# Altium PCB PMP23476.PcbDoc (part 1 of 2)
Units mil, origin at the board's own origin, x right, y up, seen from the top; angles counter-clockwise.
Board outline 965 x 1259.84 mil, 4 copper layers (Top Layer, Signal Layer 1, Signal Layer 2, Bottom Layer), stack 62 mil thick; 45 components, 25 nets, 111 pads, 20 vias.
Unrouted connection lines stored in the file: 2.
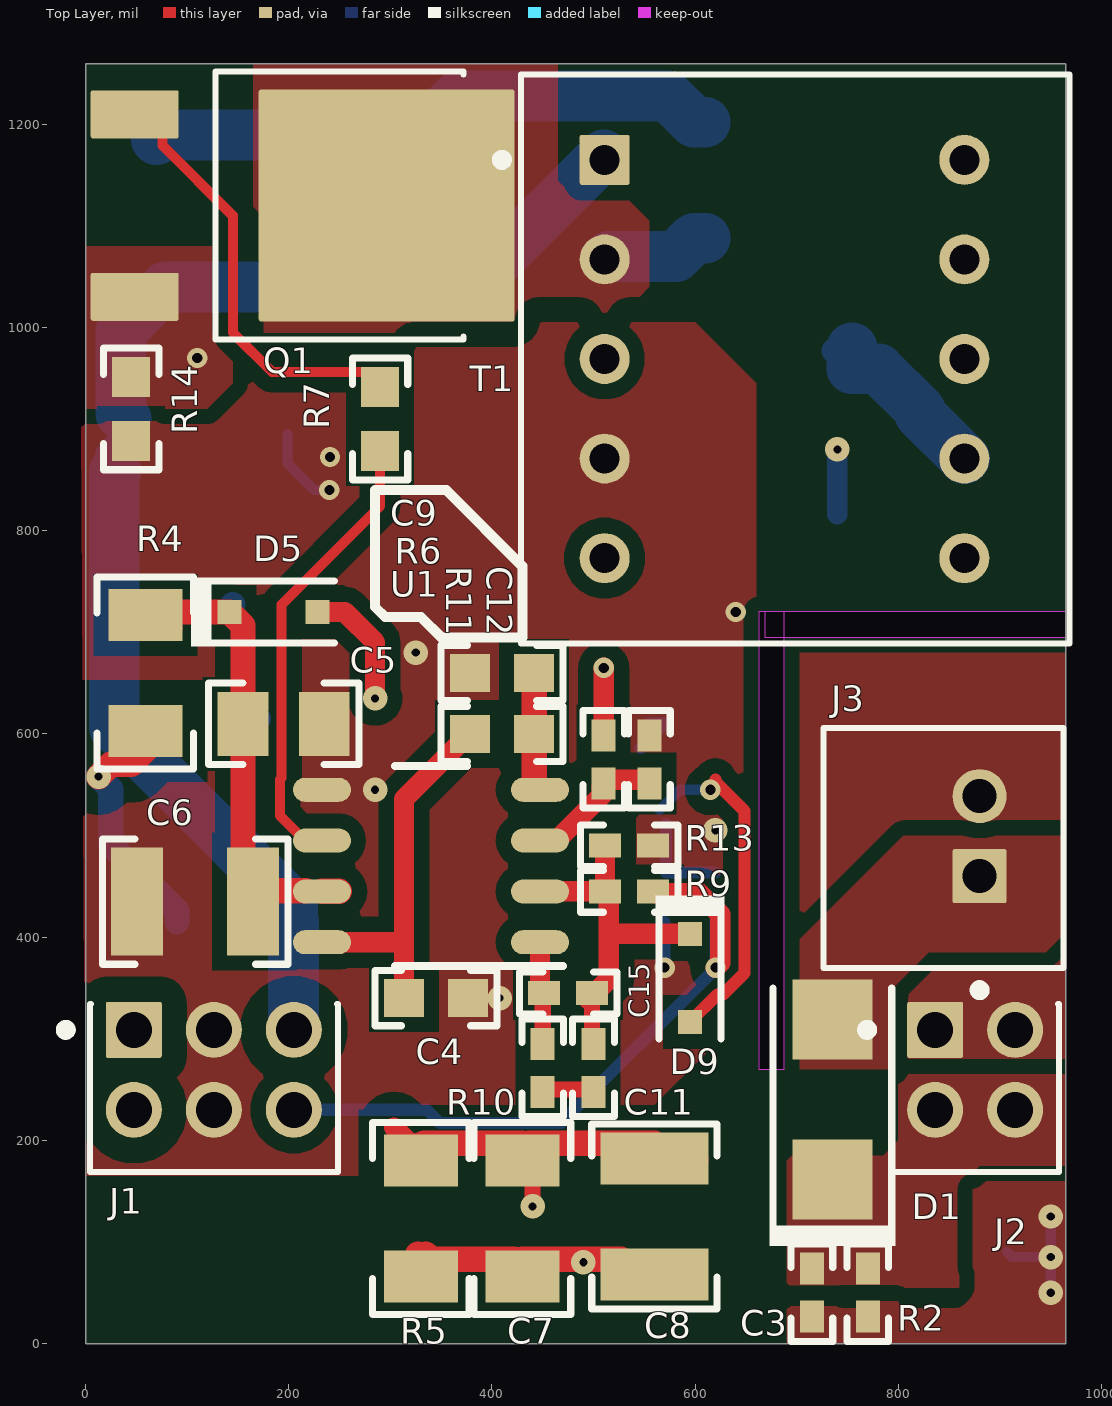
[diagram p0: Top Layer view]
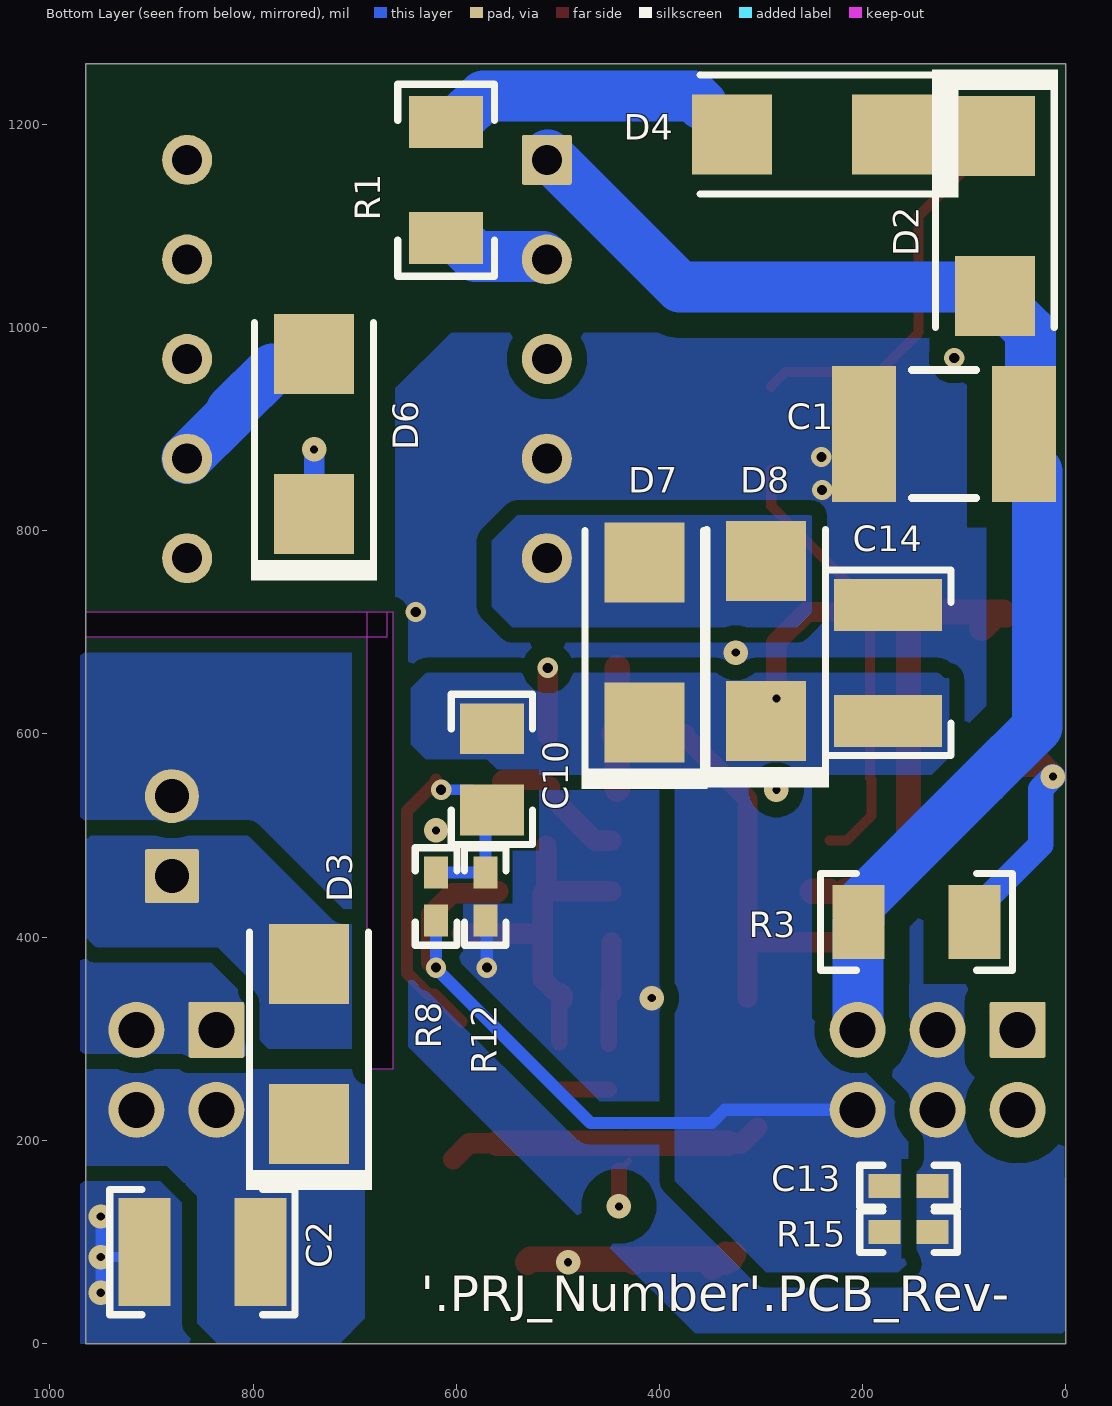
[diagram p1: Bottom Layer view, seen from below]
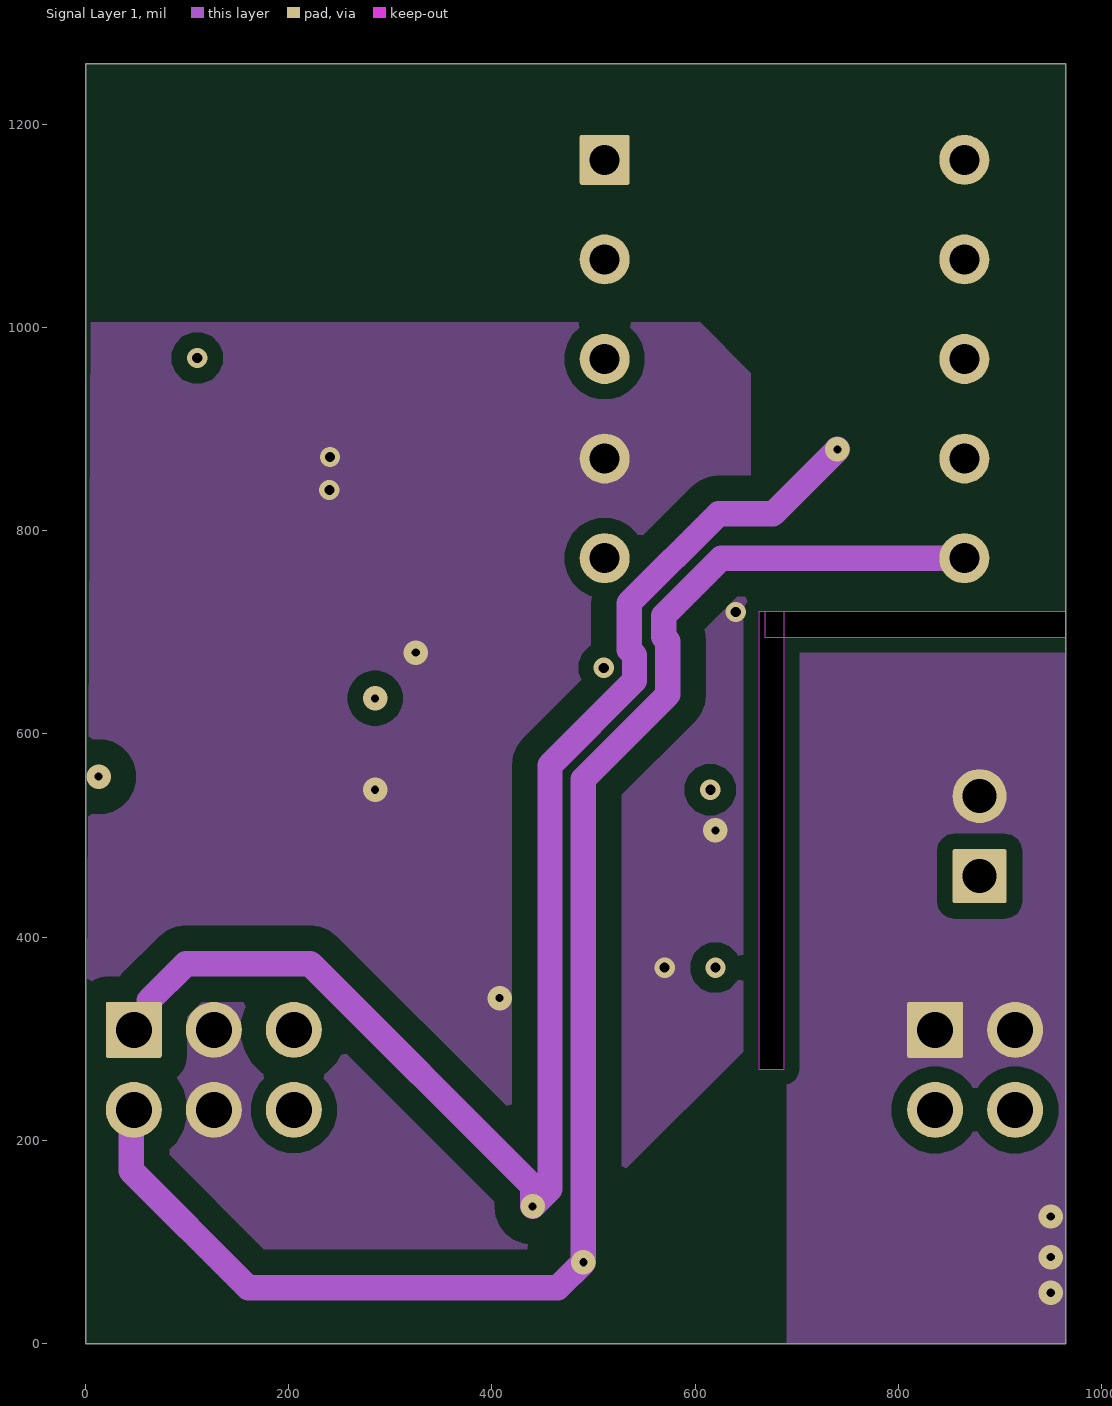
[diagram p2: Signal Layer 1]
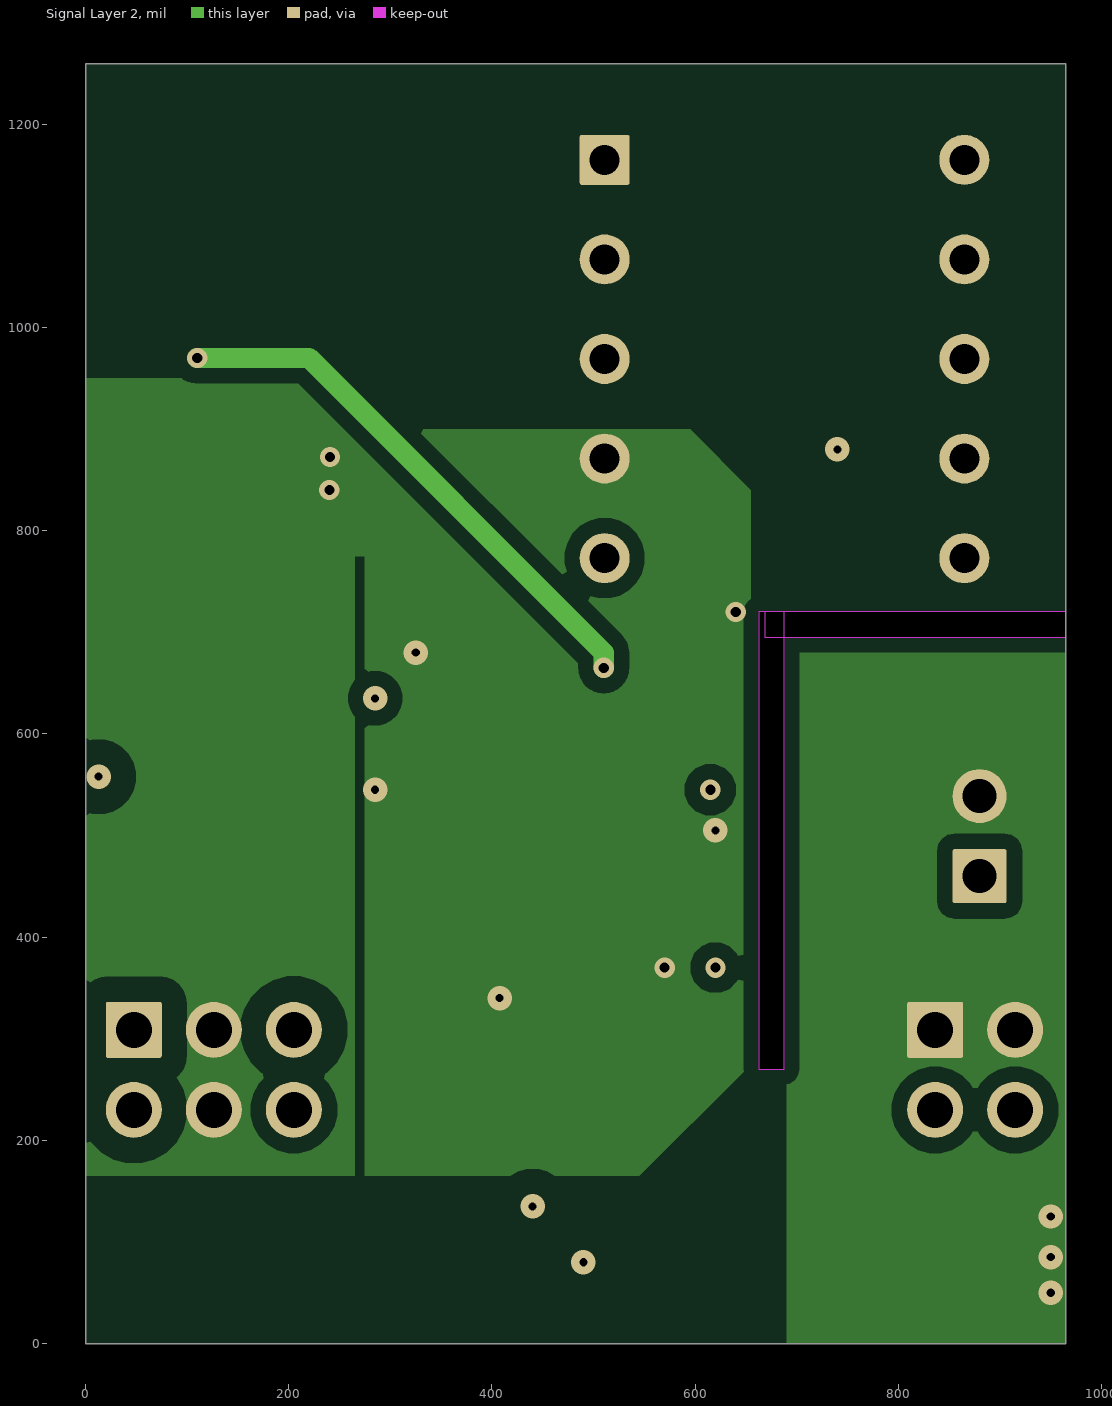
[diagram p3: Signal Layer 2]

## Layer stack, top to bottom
Top Solder: solder mask 0.4, Solder Resist, Dk 3.5
Top Layer: signal copper 1.4
Dielectric 1: prepreg 8, Dk 4.2
Dielectric1: prepreg 8, Dk 4.2
Signal Layer 1: signal copper 1.4
Dielectric 3: core 24.4, FR-4, Dk 4.2
Signal Layer 2: signal copper 1.4
Dielectric 2: prepreg 8, Dk 4.2
Dielectric 4: prepreg 8, Dk 4.2
Bottom Layer: signal copper 1.4
Bottom Solder: solder mask 0.4, Solder Resist, Dk 3.5

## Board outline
0,0 965,0 964.57,1259.84 0,1259.84
cut-out: 662.5,270 687.5,270 687.5,720 662.5,720
cut-out: 965,695 965,720 668.75,720 668.75,695

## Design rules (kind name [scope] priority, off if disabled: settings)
AcuteAngle [All] p1: minimum=4.50000000000000E+0001 checktracksonly=FALSE
AssemblyTestPointUsage [All] p1: valid=2
Clearance Clearance_1 [InNetClass('HV') vs InNet('GND_PRI')] p1: gap=25 ignorepadtopadclearanceinfootprint=TRUE except(0: Arc-Hole Track-Hole SMDPad-Hole THPad-Hole Via-Hole Fill-Hole Poly-Hole Region-Hole Text-Hole)
Clearance Clearance_Keepouts [((IsTrack Or IsArc) And Not InPoly) And IsFree and IsKeepOut vs ((IsTrack Or IsArc) And Not InPoly) And IsFree and IsKeepOut] p2: gap=0 ignorepadtopadclearanceinfootprint=FALSE
Clearance Clearance_BoardEdge_MountingHoles [OnCopper and InComponentClass('Mounting Holes') vs IsKeepOut] p3: gap=40 ignorepadtopadclearanceinfootprint=FALSE except(0: Arc-Hole Track-Hole SMDPad-Hole THPad-Hole Via-Hole Fill-Hole Poly-Hole Region-Hole Text-Hole)
Clearance Clearance_BoardEdge_Poly [OnCopper and InPoly vs IsKeepOut] p4: gap=25 ignorepadtopadclearanceinfootprint=FALSE except(0: Arc-Hole Track-Hole SMDPad-Hole THPad-Hole Via-Hole Fill-Hole Poly-Hole Region-Hole Text-Hole)
Clearance Clearance_BoardEdge [OnCopper and Not InComponentClass('Logo') and not InComponentClass('FiducialMark') and not InRegion(1000,500,4000,800) and Not IsKeepout vs IsKeepOut] p5: gap=75 ignorepadtopadclearanceinfootprint=FALSE except(0: Arc-Hole Track-Hole SMDPad-Hole THPad-Hole Via-Hole Fill-Hole Poly-Hole Region-Hole Text-Hole)
Clearance Clearance_Poly [InPolygon] p6: gap=15 ignorepadtopadclearanceinfootprint=FALSE except(0: Arc-Hole Track-Hole SMDPad-Hole THPad-Hole Via-Hole Fill-Hole Poly-Hole Region-Hole Text-Hole)
Clearance [All] p7: gap=7.87 ignorepadtopadclearanceinfootprint=FALSE except(0: Arc-Hole Track-Hole SMDPad-Hole THPad-Hole Via-Hole Fill-Hole Poly-Hole Region-Hole Text-Hole)
ComponentClearance ComponentClearance_MountingHoles_FiducialMarks [InComponentClass('Mounting Holes') vs InComponentClass('FiducialMark')] p1: gap=20 collisioncheckmode=3 verticalgap=10 showdistances=FALSE
ComponentClearance ComponentClearance_Shunt [InComponentClass('Header') vs InComponentClass('Shunt')] p2: gap=0 collisioncheckmode=3 verticalgap=0 showdistances=FALSE
ComponentClearance ComponentClearance_Logo [InComponentClass('Logo')] p3: gap=5 collisioncheckmode=3 verticalgap=10 showdistances=FALSE
ComponentClearance ComponentClearance_ScrewToNut [(HasFootprint('NY PMS 440 0025 PH')) vs (HasFootprint('Keystone_1902C'))] p4: gap=20 collisioncheckmode=3 verticalgap=100000 showdistances=FALSE
ComponentClearance ComponentClearance_MountingHoles [InComponentClass('Mounting Holes')] p5: gap=20 collisioncheckmode=3 verticalgap=10 showdistances=FALSE
ComponentClearance ComponentClearance_SmallPassives [HasFootprint('0201*') or HasFootprint('0402*') or HasFootprint('0508') or HasFootprint('0603*') or HasFootprint('0612') or HasFootprint('0805*') or HasFootprint('0815*') or HasFootprint('0830*') or HasFootprint('1206*') or HasFootprint('1210*') or HasFootprint('1808*') or HasFootprint('1812*') or HasFootprint('1825*') or HasFootprint('2010*') or HasFootprint('2220*') or HasFootprint('2225*') or HasFootprint('2512*') or HasFootprint('2728*') or HasFootprint('3518*') vs HasFootprint('0201*') or HasFootprint('0402*') or HasFootprint('0508') or HasFootprint('0603*') or HasFootprint('0612') or HasFootprint('0805*') or HasFootprint('0815*') or HasFootprint('0830*') or HasFootprint('1206*') or HasFootprint('1210*') or HasFootprint('1808*') or HasFootprint('1812*') or HasFootprint('1825*') or HasFootprint('2010*') or HasFootprint('2220*') or HasFootprint('2225*') or HasFootprint('2512*') or HasFootprint('2728*') or HasFootprint('3518*')] p6: gap=20 collisioncheckmode=3 verticalgap=20 showdistances=FALSE
ComponentClearance ComponentClearance_THtoSMT [IsThruComponent vs IsSMTComponent] p7: gap=10 collisioncheckmode=3 verticalgap=10 showdistances=FALSE
ComponentClearance ComponentClearance_THtoTH [IsThruComponent vs IsThruComponent] p8: gap=10 collisioncheckmode=3 verticalgap=10 showdistances=FALSE
ComponentClearance [All] p9: gap=10 collisioncheckmode=3 verticalgap=10 showdistances=FALSE
DiffPairsRouting [All] p1: maxlimit=100 minlimit=10 mostfreqgap=10 toplayer_minwidth=15 toplayer_maxwidth=15 toplayer_prefwidth=15 midlayer1_minwidth=15 midlayer1_maxwidth=15 midlayer1_prefwidth=15 midlayer2_minwidth=15 midlayer2_maxwidth=15 midlayer2_prefwidth=15 bottomlayer_minwidth=15 bottomlayer_maxwidth=15 bottomlayer_prefwidth=15 maxuncoupledlength=1000
FabricationTestPointUsage TestPointUsage [All] p1: valid=2 allowmultiple=FALSE
FabricationTestpoint Testpoint [All] p1: side=3 testpointundercomponent=TRUE minsize=40 maxsize=100 preferedsize=60 minholesize=0 maxholesize=40 preferedholesize=32 testpointgrid=1 allowsidetop=TRUE allowsidebottom=TRUE usegrid=TRUE gridtolerance=0.01
FanoutControl Fanout_LCC [IsLCC] p1: bgadir=Out bgaviamode=Centered fanoutstyle=Auto fanoutdirection=Alternating viagrid=1 // Fanout_LCC (Default Rule)
FanoutControl Fanout_BGA [IsBGA] p2: bgadir=Out bgaviamode=Centered fanoutstyle=Auto fanoutdirection=Alternating viagrid=1 // Fanout_BGA (Default Rule)
FanoutControl Fanout_Default [All] p4: bgadir=Out bgaviamode=Centered fanoutstyle=Auto fanoutdirection=Alternating viagrid=1 // Fanout_Default (Default Rule)
FanoutControl Fanout_Small [(CompPinCount < 5)] p5: bgadir=Out bgaviamode=Centered fanoutstyle=Auto fanoutdirection=OutThenIn viagrid=1 // Fanout_Small (Default Rule)
Height [All] p1: minheight=0 maxheight=3000 prefheight=500
HoleSize [All] p1: absolutevalues=TRUE maxlimit=251 minlimit=7 maxpercent=80.000 minpercent=20.000
MinimumAnnularRing MinimumAnnularRing_ThermalPadVias [IsVia and InAnyComponent] p1: minimumring=5.91
MinimumAnnularRing [All] p2: minimumring=4.9
MinimumSolderMaskSliver MinimumSolderMaskSliver_Logo [InComponentClass('Logo') vs InComponentClass('Logo')] p1: minsoldermaskwidth=0.7
MinimumSolderMaskSliver [All] p2: minsoldermaskwidth=2
PlaneConnect [All] p1: planeconnectstyle=Direct reliefexpansion=10 reliefentries=4 reliefconductorwidth=10 reliefairgap=10
PolygonConnect PolygonConnect_13 [All vs IsNamedPolygon('Q900_4') Or  IsNamedPolygon('Q900_4') Or  IsNamedPolygon('5V') Or  IsNamedPolygon('L900_1') Or  IsNamedPolygon('D900_2') Or  IsNamedPolygon('D902_2') Or  IsNamedPolygon('GND_PRI') Or  IsNamedPolygon('SGND') Or  IsNamedPolygon('HSS') Or  IsNamedPolygon('HSS') Or  IsNamedPolygon('C901_2') Or  IsNamedPolygon('12VPL') Or  IsNamedPolygon('C901_2') Or  IsNamedPolygon('D901_1') Or  IsNamedPolygon('D902_2') Or  IsNamedPolygon('B+') Or  IsNamedPolygon('Q900_3')] p1: connectstyle=Direct reliefconductorwidth=10 reliefentries=4 polygonreliefangle="90 Angle" airgapwidth=10
PolygonConnect PolygonConnect_12 [All vs IsNamedPolygon('C901_2') Or  IsNamedPolygon('C901_2') Or  IsNamedPolygon('GND_PRI') Or  IsNamedPolygon('5V') Or  IsNamedPolygon('B+') Or  IsNamedPolygon('D900_2') Or  IsNamedPolygon('12VPL') Or  IsNamedPolygon('D902_2') Or  IsNamedPolygon('Q900_3') Or  IsNamedPolygon('Q900_4') Or  IsNamedPolygon('D901_1') Or  IsNamedPolygon('SGND') Or  IsNamedPolygon('D902_2') Or  IsNamedPolygon('L900_1') Or  IsNamedPolygon('Q900_4')] p2: connectstyle=Direct reliefconductorwidth=10 reliefentries=4 polygonreliefangle="90 Angle" airgapwidth=10
PolygonConnect PolygonConnect_11 [All vs IsNamedPolygon('B+') Or  IsNamedPolygon('Q900_3') Or  IsNamedPolygon('12VPL') Or  IsNamedPolygon('D902_2') Or  IsNamedPolygon('D901_1') Or  IsNamedPolygon('5V') Or  IsNamedPolygon('D902_2') Or  IsNamedPolygon('Q900_4') Or  IsNamedPolygon('L900_1') Or  IsNamedPolygon('C901_2') Or  IsNamedPolygon('C901_2') Or  IsNamedPolygon('D900_2') Or  IsNamedPolygon('SGND') Or  IsNamedPolygon('Q900_4')] p3: connectstyle=Direct reliefconductorwidth=10 reliefentries=4 polygonreliefangle="90 Angle" airgapwidth=10
PolygonConnect PolygonConnect_10 [All vs IsNamedPolygon('Q900_4') Or  IsNamedPolygon('D902_2') Or  IsNamedPolygon('B+') Or  IsNamedPolygon('D901_1') Or  IsNamedPolygon('D902_2') Or  IsNamedPolygon('Q900_3')] p4: connectstyle=Direct reliefconductorwidth=10 reliefentries=4 polygonreliefangle="90 Angle" airgapwidth=10
PolygonConnect PolygonConnect_9 [All vs IsNamedPolygon('C11_1') Or  IsNamedPolygon('Vin') Or  IsNamedPolygon('Vin') Or  IsNamedPolygon('5V') Or  IsNamedPolygon('D6_2') Or  IsNamedPolygon('Q3_3') Or  IsNamedPolygon('GND2') Or  IsNamedPolygon('GND2') Or  IsNamedPolygon('GND') Or  IsNamedPolygon('Q3_4') Or  IsNamedPolygon('12V5') Or  IsNamedPolygon('GND') Or  IsNamedPolygon('12V5') Or  IsNamedPolygon('D3_1')] p5: connectstyle=Direct reliefconductorwidth=10 reliefentries=4 polygonreliefangle="90 Angle" airgapwidth=10
PolygonConnect PolygonConnect_8 [All vs IsNamedPolygon('C11_1') Or  IsNamedPolygon('Vin') Or  IsNamedPolygon('12V5') Or  IsNamedPolygon('Q3_3') Or  IsNamedPolygon('GND2') Or  IsNamedPolygon('GND2') Or  IsNamedPolygon('5V') Or  IsNamedPolygon('Q3_4') Or  IsNamedPolygon('12V5')] p6: connectstyle=Direct reliefconductorwidth=10 reliefentries=4 polygonreliefangle="90 Angle" airgapwidth=10
PolygonConnect PolygonConnect_7 [All vs IsNamedPolygon('GND2') Or  IsNamedPolygon('GND2') Or  IsNamedPolygon('5V') Or  IsNamedPolygon('12V5') Or  IsNamedPolygon('12V5') Or  IsNamedPolygon('C11_1')] p7: connectstyle=Direct reliefconductorwidth=10 reliefentries=4 polygonreliefangle="90 Angle" airgapwidth=10
PolygonConnect PolygonConnect_6 [All vs IsNamedPolygon('GND2') Or  IsNamedPolygon('SGND') Or  IsNamedPolygon('GND1') Or  IsNamedPolygon('C901_1') Or  IsNamedPolygon('SGND') Or  IsNamedPolygon('GND2') Or  IsNamedPolygon('GND1')] p8: connectstyle=Direct reliefconductorwidth=10 reliefentries=4 polygonreliefangle="90 Angle" airgapwidth=10
PolygonConnect PolygonConnect_5 [All vs IsNamedPolygon('GND1') Or  IsNamedPolygon('GND1')] p9: connectstyle=Direct reliefconductorwidth=10 reliefentries=4 polygonreliefangle="90 Angle" airgapwidth=10
PolygonConnect PolygonConnect_4 [All vs IsNamedPolygon('C21_1') Or  IsNamedPolygon('C5_1') Or  IsNamedPolygon('C12_2') Or  IsNamedPolygon('C2_2') Or  IsNamedPolygon('C13_1') Or  IsNamedPolygon('C28_1') Or  IsNamedPolygon('C6_1') Or  IsNamedPolygon('GND') Or  IsNamedPolygon('GND2') Or  IsNamedPolygon('C14_1') Or  IsNamedPolygon('C13_1') Or  IsNamedPolygon('Q1_3') Or  IsNamedPolygon('C14_1') Or  IsNamedPolygon('C5_1') Or  IsNamedPolygon('GND2') Or  IsNamedPolygon('C28_1') Or  IsNamedPolygon('D5_2') Or  IsNamedPolygon('D6_2') Or  IsNamedPolygon('D2_1') Or  IsNamedPolygon('C12_2') Or  IsNamedPolygon('D2_1') Or  IsNamedPolygon('C4_1') Or  IsNamedPolygon('C4_1') Or  IsNamedPolygon('C2_2') Or  IsNamedPolygon('GND') Or  IsNamedPolygon('C33_1') Or  IsNamedPolygon('C9_1')] p10: connectstyle=Direct reliefconductorwidth=10 reliefentries=4 polygonreliefangle="90 Angle" airgapwidth=10
PolygonConnect PolygonConnect_3 [All vs IsNamedPolygon('C28_1') Or  IsNamedPolygon('C12_2') Or  IsNamedPolygon('C28_1') Or  IsNamedPolygon('C9_1') Or  IsNamedPolygon('D5_2') Or  IsNamedPolygon('C12_2') Or  IsNamedPolygon('C2_2') Or  IsNamedPolygon('C14_1') Or  IsNamedPolygon('C4_1') Or  IsNamedPolygon('C14_1') Or  IsNamedPolygon('D6_2') Or  IsNamedPolygon('GND2') Or  IsNamedPolygon('Q1_3') Or  IsNamedPolygon('C5_1') Or  IsNamedPolygon('D2_1') Or  IsNamedPolygon('C4_1') Or  IsNamedPolygon('C13_1') Or  IsNamedPolygon('C5_1') Or  IsNamedPolygon('C13_1') Or  IsNamedPolygon('C33_1') Or  IsNamedPolygon('D2_1') Or  IsNamedPolygon('GND') Or  IsNamedPolygon('GND') Or  IsNamedPolygon('GND2') Or  IsNamedPolygon('C2_2') Or  IsNamedPolygon('C6_1') Or  IsNamedPolygon('C21_1')] p11: connectstyle=Direct reliefconductorwidth=10 reliefentries=4 polygonreliefangle="90 Angle" airgapwidth=10
PolygonConnect PolygonConnect_2 [All vs IsNamedPolygon('C21_1') Or  IsNamedPolygon('C4_1') Or  IsNamedPolygon('D5_2') Or  IsNamedPolygon('C5_1') Or  IsNamedPolygon('C14_1') Or  IsNamedPolygon('C13_1') Or  IsNamedPolygon('C4_1') Or  IsNamedPolygon('C33_1') Or  IsNamedPolygon('C12_2') Or  IsNamedPolygon('D2_1') Or  IsNamedPolygon('C2_2') Or  IsNamedPolygon('C28_1') Or  IsNamedPolygon('C12_2') Or  IsNamedPolygon('D2_1') Or  IsNamedPolygon('C5_1') Or  IsNamedPolygon('Q1_3') Or  IsNamedPolygon('GND') Or  IsNamedPolygon('D6_2') Or  IsNamedPolygon('C6_1') Or  IsNamedPolygon('C2_2') Or  IsNamedPolygon('C14_1') Or  IsNamedPolygon('C28_1') Or  IsNamedPolygon('C13_1') Or  IsNamedPolygon('C9_1') Or  IsNamedPolygon('GND')] p12: connectstyle=Direct reliefconductorwidth=10 reliefentries=4 polygonreliefangle="90 Angle" airgapwidth=10
PolygonConnect PolygonConnect_1 [All vs IsNamedPolygon('C28_1') Or  IsNamedPolygon('D5_2') Or  IsNamedPolygon('C5_1') Or  IsNamedPolygon('C5_1') Or  IsNamedPolygon('D2_1') Or  IsNamedPolygon('C21_1') Or  IsNamedPolygon('C9_1') Or  IsNamedPolygon('C4_1') Or  IsNamedPolygon('C14_1') Or  IsNamedPolygon('C28_1') Or  IsNamedPolygon('C6_1') Or  IsNamedPolygon('C12_2') Or  IsNamedPolygon('C33_1') Or  IsNamedPolygon('C4_1') Or  IsNamedPolygon('C13_1') Or  IsNamedPolygon('C12_2') Or  IsNamedPolygon('D6_2') Or  IsNamedPolygon('C2_2') Or  IsNamedPolygon('C14_1') Or  IsNamedPolygon('D2_1') Or  IsNamedPolygon('C2_2') Or  IsNamedPolygon('C13_1')] p13: connectstyle=Direct reliefconductorwidth=10 reliefentries=4 polygonreliefangle="90 Angle" airgapwidth=10
PolygonConnect [All] p14: connectstyle=Direct reliefconductorwidth=10 reliefentries=4 polygonreliefangle="90 Angle" airgapwidth=10
RoutingVias ThermalPadVias [IsVia and InAnyComponent] p1: holewidth=7.87 width=19.68 viastyle="Through Hole" minholewidth=7.87 minwidth=19.68 maxholewidth=12.99 maxwidth=23.62
RoutingVias [All] p2: holewidth=16 width=34 viastyle="Through Hole" minholewidth=7.87 minwidth=20 maxholewidth=40 maxwidth=65
SilkToBoardRegionClearance [Not ((IsComment or IsDesignator) And (Hide <> 'False')) and not InRegion(1000,500,4000,800)] p1:
SilkToSilkClearance SilkToSilkClearance_Pb-FreeLogo [(HasFootprint('Pb-Free_Overlay_Medium') OR HasFootprint('Pb-Free_Overlay_Small')) vs (HasFootprint('Pb-Free_Overlay_Medium') OR HasFootprint('Pb-Free_Overlay_Small'))] p1: silktosilkclearance=0
SilkToSilkClearance [All] p2: silktosilkclearance=1
SilkToSolderMaskClearance "Silk to Solder Mask Opening" [All] p1: minsilkscreentomaskgap=1 clearancetoexposedcopper=FALSE
SolderMaskExpansion [All] p1: expansion=1.97 istentingtop=FALSE
Width [All] p1: maxlimit=100 minlimit=6 preferedwidth=10 checkconnectedcopper=TRUE
14 further rules are at their usual default settings.

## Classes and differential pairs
component class NoTherm: C1
net class HV: 12Vp_h B+ HSS NetD2_1 NetD4_2 NetD6_2 NetQ1_4 NetR3_2

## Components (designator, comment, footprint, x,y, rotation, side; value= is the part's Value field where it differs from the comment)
C1 "GRM43DR72J104KW01L" 1812 120,895 r0 bottom value=0.1uF
C2 "GRM32EC81C476ME15L" 1210_270 850,90 r0 bottom value=47uF
C3 "GRM155R71H104ME14D" 0402 715,50 r270 top value=0.1uF
C4 "GMK107BJ105KA-T" 0603 345,340 r0 top value=1uF
C5 "CL21B105KBFNNNE" 0805_HV 195,610 r0 top value=1uF
C6 "GRM32ER61C476KE15L" 1210_270 107.91,435 r0 top value=47uF
C7 "12063D225KAT2A" 1206 430,122.91 r270 top value=2.2uF
C8 "GRM32ER61C476KE15L" 1210_270 560,125 r90 top value=47uF
C9 "06031C221KAT2A" 0603 410,660 r0 top value=220pF
C10 "0805ZD475KAT2A" 0805_HV 565,565 r270 bottom value=4.7uF
C11 "GRM155R61C223KA01D" 0402 500,271.38 r90 top value=0.022uF
C12 "C0402C821J5GAC7867" 0402 555,575 r90 top value=820pF
C13 "885012205037" 0402 155,155 r180 bottom value=0.1uF
C14 "GRM32ER61C476KE15L" 1210_270 175,670 r270 bottom value=47uF
C15 "GRM1555C1E391JA01D" 0402 475,345 r0 top value=390pF
D1 "SK215ATR" SMA 735,240 r90 top value=150V
D2 "SMAJ130A" SMA 70,1110 r270 bottom value=130V
D3 "SK215ATR" SMA 745,295 r90 bottom value=150V
D4 "US1M-13-F" SMA 250,1190 r0 bottom value=1.7V
D5 "BAS20HT1G" sod-323 185,720 r0 top
D6 "SK215ATR" SMA 740,895 r90 bottom value=150V
D7 "SK215ATR" SMA 415,690 r90 bottom value=150V
D8 "SK215ATR" SMA 295,691.26 r90 bottom value=150V
D9 "MMDL914-TP" sod-323 595,360 r270 top value=100V
J1 "877600616" FP-877600616_HDR6-MFG 126.26,251.65 r0 top
J2 "877600416" FP-877600416_HDR4-MFG 875.63,251.65 r0 top
J3 "292133-2" FP-292133-2_HDR2-MFG 844.57,487.56 r270 top
Q1 "IPD80R1K2P7ATMA1" FP-IPD80R1K2P7ATMA1_DPAK-MFG 250,1120 r270 top
R1 "CRCW120651R0JNEA" 1206 610,1145 r270 bottom value=51
R2 "CRCW04027K50FKED" 0402 770,50 r90 top value=7.50k
R3 "CRCW1206200KJNEA" 1206 147.09,415 r180 bottom value=200k
R4 "CRCW1206200KJNEA" 1206 58.8,660 r90 top value=200k
R5 "CRCW12062K00JNEA" 1206 330,122.91 r90 top value=2.0k
R6 "RC0603FR-0727K4L" 0603 410,600 r180 top value=27.4k
R7 "CRCW06030000Z0EA" 0603 290,910 r90 top value=0
R8 "CRCW04021M00JNED" 0402 620,440 r270 bottom value=1.0Meg
R9 "CRCW04029K53FKED" 0402 535,445 r0 top value=9.53k
R10 "CRCW0402200KFKED" 0402 450,271.38 r90 top value=200k
R11 "CRCW0402499RFKED" 0402 510,575 r90 top value=499
R12 "CRCW040210K0FKED" 0402 571.46,440 r90 bottom value=10.0k
R13 "CRCW04022K49FKED" 0402 535,490 r180 top value=2.49k
R14 "RC0603FR-073R9L" 0603 45,920 r90 top value=3.9
R15 "CRCW04027K50JNED" 0402 155,110 r0 bottom value=7.5k
T1 "RLTI-1442" FP-RLTI-1442_PTH_XFRMR_0_IN51_0IN56-MFG 698.5,969 r0 top
U1 "UCC3813D-4" D0008A_N 340,470 r180 top

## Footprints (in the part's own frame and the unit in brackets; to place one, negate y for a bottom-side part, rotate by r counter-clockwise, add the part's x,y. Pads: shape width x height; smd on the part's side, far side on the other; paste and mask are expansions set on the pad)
0402 [mm] "0402 from SM-752 data"
  rect 0.8x0.6 smd: 1(-0.6,0) 2(0.6,0)
  silkscreen extent -1.22,-0.52 1.22,0.52, body extent -0.55,-0.3 0.55,0.3, height 0.6
0603 [mm] "0603 from SM-752 data"
  rect 1x0.95 smd: 1(-0.8,0) 2(0.8,0)
  silkscreen extent -1.52,-0.69 1.52,0.69, body extent -0.87,-0.47 0.87,0.47, height 1
0805_HV [mil] "0805 with 30mil clearance between pads"
  rect 50x63 smd: 1(-40,0) 2(40,0)
  silkscreen extent -74,-40 74,40, body extent -43,-29 43,29, height 57
1206 [mm] "1206 from SM-752 data"
  rect 1.3x1.85 smd: 1(-1.45,0) 2(1.45,0)
  silkscreen extent -2.4,-1.21 2.4,1.21, body extent -1.7,-0.9 1.7,0.9, height 1.35
1210_270 [mm] "1210"
  rect 1.3x2.7 smd: 1(-1.45,0) 2(1.45,0)
  silkscreen extent -2.32,-1.57 2.32,1.57, body extent -1.7,-1.35 1.7,1.35, height 2.7
1812 [mm]
  rect 1.6x3.4 smd: 1(-2,0) 2(2,0)
  silkscreen extent -0.8,-1.6 0.8,1.6, body extent -2.4,-1.7 2.4,1.7, height 1.35
D0008A_N [mm] "SOIC, 8-Leads, Body 4.9x3.9mm, Pitch 1.27mm, IPC Medium Density"
  oval 1.45x0.6 smd: 1(-2.725,1.905) 2(-2.725,0.635) 3(-2.725,-0.635) 4(-2.725,-1.905) 5(2.725,-1.905) 6(2.725,-0.635) 7(2.725,0.635) 8(2.725,1.905)
  silkscreen extent -3.3,-2.5 0.9,2.5, body extent -3,-2.45 3,2.45, height 1.63
FP-292133-2_HDR2-MFG [mm]
  rrect7% 1.35x1.35 hole 0.85 paste-1000 mask+0: 1(0.7,0.9)
  round 1.35 hole 0.85 paste-1000 mask+0: 2(-1.3,0.9)
  silkscreen extent -3,-3 3.67,3, body extent -3.1,-3.1 3.1,3.1, height 0.25
FP-877600416_HDR4-MFG [mm]
  rrect7% 1.4x1.4 hole 0.9 paste-1000 mask+0: 1(-1,1.45)
  round 1.4 hole 0.9 paste-1000 mask+0: 2(-1,-0.55) 3(1,1.45) 4(1,-0.55)
  silkscreen extent -2.82,-2.1 2.1,2.1, body extent -2.2,-6.4 2.2,2.25, height 0.25
FP-877600616_HDR6-MFG [mm]
  rrect7% 1.4x1.4 hole 0.9 paste-1000 mask+0: 1(-2,1.45)
  round 1.4 hole 0.9 paste-1000 mask+0: 2(-2,-0.55) 3(0,1.45) 4(0,-0.55) 5(2,1.45) 6(2,-0.55)
  silkscreen extent -3.82,-2.1 3.1,2.1, body extent -3.2,-6.4 3.2,2.25, height 0.25
FP-IPD80R1K2P7ATMA1_DPAK-MFG [mm]
  rrect8% 1.2x2.2 smd paste-1000 mask+0: 1(-2.28,-5.12) 3(2.28,-5.12)
  rrect2% 5.8x6.4 smd paste-1000 mask+0: 4(0,1.18)
  silkscreen extent -3.35,-3.1 3.35,3.1, body extent -3.45,-6.32 3.45,4.48, height 0.25
FP-RLTI-1442_PTH_XFRMR_0_IN51_0IN56-MFG [mm]
  rrect8% 1.25x1.25 hole 0.75 paste-1000 mask+0: 1(-4.763,4.978)
  round 1.25 hole 0.75 paste-1000 mask+0: 2(-4.763,2.489) 3(-4.763,0) 4(-4.763,-2.489) 5(-4.763,-4.978) 6(4.229,-4.978) 7(4.229,-2.489) 8(4.229,0) 9(4.229,2.489) 10(4.229,4.978)
  silkscreen extent -7.46,-7.11 6.86,7.11, body extent -6.96,-7.21 6.96,7.21, height 0.25
SMA [mm] "Molded Diode, 2-Leads, Body 4.3x2.6mm, IPC Medium Density, based on OnSemi component dimensions and land pattern"
  rect 2x2 smd: 1(-2,0) 2(2,0)
  silkscreen extent -3.66,-1.57 2.79,1.57, body extent -2.6,-1.3 2.6,1.3, height 2.42
sod-323 [mm] "NXP recommended land pattern"
  rect 0.6x0.6 smd paste-0.05: 1(-1.1,0) 2(1.1,0)
  silkscreen extent -2.06,-0.86 1.53,0.86, body extent -1.3,-0.67 1.3,0.68, height 1.1

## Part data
C1: "CAP, CERM, 0.1uF, 630V, +/-10%, X7R, 1812", Alternate Manufacturer=-, Cap_Case=1812, Manufacturer=MuRata, Supplier Part Number 1=490-3518-1-ND, TempCo=X7R, Tolerance_%=10, Value1=?, Value2=630V, ValueDisplayed=0.1µF
C2: library part CMP-0009201-2, "CAP, CERM, 47 uF, 16 V, +/- 20%, X6S, 1210", Cap_Case=1210, Manufacturer=MuRata, Supplier Part Number 1=490-9968-1-ND, TempCo=X6S, Tolerance_%=20%, Value1=Unknown, Value2=16V, ValueDisplayed=47uF
C3: library part CMP-0006675-2, "CAP, CERM, 0.1 uF, 50 V, +/- 20%, X7R, 0402", Cap_Case=0402, Manufacturer=MuRata, Supplier Part Number 1=490-10701-1-ND, TempCo=X7R, Tolerance_%=20%, Value1=Unknown, Value2=50V, ValueDisplayed=0.1uF
C4: library part CMP-0007150-5, "CAP, CERM, 1 uF, 35 V, +/- 10%, X5R, 0603", Cap_Case=0603, Manufacturer="Taiyo Yuden", Supplier Part Number 1=587-1437-1-ND, TempCo=X5R, Tolerance_%=10%, Value1=Unknown, Value2=35V, ValueDisplayed=1uF
C5: "CAP, CERM, 1 µF, 50 V, +/- 10%, X7R, 0805", Cap_Case=0805, Manufacturer="Samsung Electro-Mechanics", TempCo=X7R, Tolerance_%=10, Value1=Unknown, Value2=50V, ValueDisplayed=1µF
C6 C8 C14: "CAP, CERM, 47 µF, 16 V, +/- 10%, X5R, 1210", Cap_Case=1210, Manufacturer=MuRata, Supplier Part Number 1=GRM32ER61C476KE15L-ND, TempCo=X5R, Tolerance_%=10, Value1=Unknown, Value2=16V, ValueDisplayed=47µF
C7: "CAP, CERM, 2.2 µF, 25 V, +/- 10%, X5R, 1206", Cap_Case=1206, Manufacturer=AVX, Supplier Part Number 1=478-1569-1-ND, TempCo=X5R, Tolerance_%=10, Value1="0.016 ohm", Value2=25V, ValueDisplayed=2.2µF
C9: "CAP, CERM, 220pF, 100V, +/-10%, X7R, 0603", Cap_Case=0603, Manufacturer=AVX, Supplier Part Number 1=478-1195-1-ND, TempCo=X7R, Tolerance_%=10, Value1="0.579 ohm", Value2=100V, ValueDisplayed=220pF
C10: "CAP, CERM, 4.7uF, 10V, +/-10%, X5R, 0805", Cap_Case=0805, Manufacturer=AVX, Supplier Part Number 1=478-1415-1-ND, TempCo=X5R, Tolerance_%=10, Value1="0.007 ohm", Value2=10V, ValueDisplayed=4.7µF
C11: "CAP, CERM, 0.022 µF, 16 V, +/- 10%, X5R, 0402", Cap_Case=0402, Manufacturer=MuRata, Supplier Part Number 1=GRM155R61C223KA01D-ND, TempCo=X5R, Tolerance_%=10, Value1=Unknown, Value2=16V, ValueDisplayed=0.022µF
C12: library part GRM1555C1H681JA01D, "CAP, CERM, 92- pF, 50 V, +/- 5%, C0G/NP0, 0402 *manually edited part*", Cap_Case=0402, Manufacturer=Kemet, Supplier Part Number 1=399-C0402C821J5GAC7867TR-ND, TempCo=C0G/NP0, Tolerance_%=5, Value1=Unknown, Value2=50V, ValueDisplayed=820pF
C13: "CAP, CERM, 0.1 µF, 16 V, +/- 10%, X7R, 0402", Cap_Case=0402, Manufacturer="Wurth Elektronik", Supplier Part Number 1=732-7532-1-ND, TempCo=X7R, Tolerance_%=10, Value1=Unknown, Value2=16V, ValueDisplayed=0.1µF
C15: library part CMP-0006381-2, "CAP, CERM, 390 pF, 25 V, +/- 5%, C0G/NP0, 0402", Cap_Case=0402, Manufacturer=MuRata, Supplier Part Number 1=GRM1555C1E391JA01D-ND, TempCo=C0G/NP0, Tolerance_%=5%, Value1=Unknown, Value2=25V, ValueDisplayed=390pF
D1 D3 D6 D7 D8: library part CMP-0028966-2, "Diode, Schottky, 150 V, 2 A, SMA", Manufacturer="SMC Diode Solutions", Value1=2A, Value2=0.95V
D2: library part SMAJ120A, "DIODE TVS 130V 400W UNI 5% SMD", Manufacturer=Littelfuse, Power_W=400, Value1=400W
D4: "Diode, Ultrafast, 1000V, 1A, SMA", Manufacturer="Diodes Inc.", Supplier Part Number 1=US1M-FDICT-ND, Value1=1A, Value2=1000V
D5: library part BAS316,115, "DIODE SWITCH 200V 200MA SOD323", Supplier Part Number 1=BAS20HT1GOSTR-ND, Value1=0.25A, Value2=100V
D9: "Diode, Switching, 100V, 0.2A, SOD-323", Manufacturer="Micro Commercial Components", Supplier Part Number 1=MMDL914-TPMSCT-ND, Value1=0.2A, Value2=1V
J1: library part CMP-0095636-1, "Connector Header Through Hole, Right Angle 6 position 0.079\" (2.00mm)", Current_A=2A, Digikey Part Number=WM18613-ND, Manufacturer=Molex, Mouser Part Number=538-87760-0616, Operating Temperature Range="-55°C to +105°C", Voltage_V=125V
J2: library part CMP-0095635-1, "Connector Header Through Hole, Right Angle 4 position 0.079\" (2.00mm)", Current_A=2A, Digikey Part Number=WM18612-ND, Manufacturer=Molex, Mouser Part Number=538-87760-0416, Operating Temperature Range="-55°C to +105°C", Voltage_V=125V
J3: library part CMP-0095293-1, "Connector Header Through Hole 2 position 0.079\" (2.00mm)", Current_A=4A, Digikey Part Number=A100944-ND, Manufacturer="TE Connectivity", Mouser Part Number=571-292133-2, Operating Temperature Range="-30°C to +105°C", Voltage_V=125V
Q1: library part CMP-0098249-1, "MOSFET N-Channel 800 V 4.5A (Tc) 37W (Tc) Surface Mount PG-TO252-3", Digikey Part Number=IPD80R1K2P7ATMA1CT-ND, Drain To Source Breakdown Voltage=800V, Input Capacitace At Vds="300pF @ 500V", Manufacturer="Infineon Technologies", Mouser Part Number=726-IPD80R1K2P7ATMA1, Operating Temperature Range="-55°C to +150°C", Power_W=37W, Pulse Drain Current=11A, Typ Forward Diode Voltage=0.9V
R1: "RES, 51, 5%, 0.25 W, 1206", Manufacturer=Vishay-Dale, Power_W=0.25, Supplier Part Number 1=541-51ECT-ND, TempCo="200 ppm/C", Tolerance_%=5, Value1=5%, Value2=0.25W, Value_Code=51R0, ValueDisplayed=51
R2: library part CMP-0026555-2, "RES, 7.50 k, 1%, 0.063 W, AEC-Q200 Grade 0, 0402", Manufacturer=Vishay-Dale, Power_W=63mW, Supplier Part Number 1=541-7.50KLCT-ND, TempCo="100 ppm/C", Tolerance_%=1%, Value2=0.063W, Value_Code=7k50, ValueDisplayed=7.50k
R3 R4: library part CMP-0018624-3, "RES, 200 k, 5%, 0.25 W, AEC-Q200 Grade 0, 1206", Manufacturer=Vishay-Dale, Power_W=250mW, Supplier Part Number 1=541-200KECT-ND, TempCo="200 ppm/C", Tolerance_%=5%, Value2=0.25W, Value_Code=200k
R5: "RES, 2.0 k, 5%, 0.25 W, 1206", Manufacturer=Vishay-Dale, Power_W=0.25, Supplier Part Number 1=541-2.0KECT-ND, TempCo="200 ppm/C", Tolerance_%=5, Value1=5%, Value2=0.25W, Value_Code=2k00, ValueDisplayed=2.0k
R6: library part CMP-0022965-5, "RES, 27.4 k, 1%, 0.1 W, 0603", Manufacturer=Yageo, Power_W=100mW, Supplier Part Number 1=311-27.4KHRCT-ND, TempCo="100 ppm/C", Tolerance_%=1%, Value2=0.1W, Value_Code=27k4, ValueDisplayed=27.4k
R7: "RES, 0, 5%, 0.1 W, 0603", Manufacturer=Vishay-Dale, Power_W=0.1, Supplier Part Number 1=541-0.0GCT-ND, TempCo="200 ppm/C", Tolerance_%=5, Value1=5%, Value2=0.1W, Value_Code=0000, ValueDisplayed=0
R8: "RES, 1.0 M, 5%, 0.063 W, 0402", Manufacturer=Vishay-Dale, Power_W=0.063, Supplier Part Number 1=541-1.0MJCT-ND, TempCo="200 ppm/C", Tolerance_%=5, Value1=5%, Value2=0.063W, Value_Code=1M00, ValueDisplayed=1.0M
R9: "RES, 9.53 k, 1%, 0.063 W, 0402", Manufacturer=Vishay-Dale, Power_W=0.063, Supplier Part Number 1=541-9.53KLCT-ND, TempCo="100 ppm/C", Tolerance_%=1, Value1=1%, Value2=0.063W, Value_Code=9k53, ValueDisplayed=9.53k
R10: "RES, 200 k, 1%, 0.063 W, 0402", Manufacturer=Vishay-Dale, Power_W=0.063, Supplier Part Number 1=541-200KLCT-ND, TempCo="100 ppm/C", Tolerance_%=1, Value1=1%, Value2=0.063W, Value_Code=200k
R11: "RES, 499, 1%, 0.063 W, 0402", Manufacturer=Vishay-Dale, Power_W=0.063, Supplier Part Number 1=541-499LCT-ND, TempCo="100 ppm/C", Tolerance_%=1, Value1=1%, Value2=0.063W, Value_Code=499R, ValueDisplayed=499
R12: "RES, 10.0 k, 1%, 0.063 W, 0402", Manufacturer=Vishay-Dale, Power_W=0.063, Supplier Part Number 1=541-10.0KLCT-ND, TempCo="100 ppm/C", Tolerance_%=1, Value1=1%, Value2=0.063W, Value_Code=10k0, ValueDisplayed=10.0k
R13: "RES, 2.49 k, 1%, 0.063 W, 0402", Manufacturer=Vishay-Dale, Power_W=0.063, Supplier Part Number 1=541-2.49KLCT-ND, TempCo="100 ppm/C", Tolerance_%=1, Value1=1%, Value2=0.063W, Value_Code=2k49, ValueDisplayed=2.49k
R14: library part CRCW060310R0FKEA, "RES, 3.9, 1%, 0.1 W, 0603 *manually edited*", Manufacturer=Yageo, Power_W=0.1, Supplier Part Number 1=13-RC0603FR-073R9LTR-ND, TempCo="100 ppm/C", Tolerance_%=1, Value1=1%, Value2=0.1W, Value_Code=10R0, ValueDisplayed=3.9
R15: "RES, 7.5 k, 5%, 0.063 W, 0402", Manufacturer=Vishay-Dale, Power_W=0.063, Supplier Part Number 1=541-7.5KJCT-ND, TempCo="200 ppm/C", Tolerance_%=5, Value1=5%, Value2=0.063W, Value_Code=7k50, ValueDisplayed=7.5k
T1: library part CMP-0095385-1, "Flyback for PMP23126", Manufacturer="Renco Electronics", Operating Temperature Range=to, Voltage_Isolation_Vrms=1500VDC
U1: library part UCC28C42DR, "IC REG CTRLR PWM CM 8SOIC", Alternate Manufacturer="Texas Instruments"

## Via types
v1: diameter 24, hole 8, Top Layer to Bottom Layer, tented both sides, 12 vias
v2: diameter 20, hole 10, Top Layer to Bottom Layer, 8 vias

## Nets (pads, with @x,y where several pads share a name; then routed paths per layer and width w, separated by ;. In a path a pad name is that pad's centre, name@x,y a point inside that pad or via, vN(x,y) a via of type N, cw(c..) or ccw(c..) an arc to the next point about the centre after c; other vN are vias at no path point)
12Vp: C10.1 C13.1 C14.2 D5.2 D7.1 D8.1 J1.6 R8.2 R9.2 R15.2 | length 826.1
  Top Layer w20: D5.2@228.07,720 D5.2@228.31,720 ; D5.2@240,720 255,720 285,690 v1(285,635) ; R9.2@558.62,445 560.43,443.19 604.02,443.19 624.68,422.52 624.68,374.68 v2(620,370)
  Bottom Layer w12: J1.6@210,235 215,230 335.76,230 348.76,217 467.84,217 620,369.16 v2(620,370) R8.2@620,416.38 ; C10.1@546.14,586 C10.1@570.14,610 ; C10.1@555.14,610 C10.1@570,610
  Bottom Layer w25: C14.2@165,610 C14.2@170,615
12Vp_h: C7.1 C8.2 D6.1 J1.1 R5.2 | length 1893.7
  Top Layer w6: C7.1@430,180 C7.1@440,170
  Top Layer w10: C7.1@430,197.09 C7.1@436.54,197.09
  Top Layer w16: v1(440,135) C7.1@440,170
  Top Layer w20: J1.1@40,315 53.78,315 J1.1@65.08,326.3 ; 303.58,212.68 319.17,197.09 R5.2@330,197.09 ; C8.2@560,197.09 587.56,197.09 C8.2@603.15,181.5
  Top Layer w25: R5.2@332.91,197.09 C7.1@430,197.09 ; C7.1@436.54,197.09 C8.2@560,197.09
  Signal Layer 1 w25: J1.1@48.78,310 62.58,323.8 62.58,337.58 98.8,373.8 221.2,373.8 440,155 v1(440,135) 457.13,152.13 457.13,569.17 540.37,652.42 540.37,677.58 535,682.96 535,728.67 622.98,816.65 676.65,816.65 v1(740,880)
  Bottom Layer w20: D6.1@740,816.26 v1(740,880)
12Vs: C2.1 C3.1 D1.1 D3.1 J2.2 J2.4 R2.2
B+: C1.1 D2.2 J1.5 R3.1 T1.1 | length 1296.3
  Bottom Layer w25: C1.1@22.26,876 C1.1@41.26,895 C1.1@35,901.26 ; D2.2@73.24,1034.5 D2.2@74.5,1034.5
  Bottom Layer w50: C1.1@30,860 28.19,858.19 28.19,606.81 80.55,554.45 203.58,431.42 203.58,415.59 204.59,414.59 204.59,310.41 J1.5@205,310 ; C1.1@40,910 35,915 35,996.26 D2.2@70,1031.26 73.24,1034.5 78.74,1040 380,1040 T1.1@510,1170
GND_PRI: C1.2 C4.2 C5.2 C6.1 C9.1 C12.2 C13.2 C14.1 J1.3 J1.4 R12.1 R13.1 R14.1 R15.1 T1.4 U1.5 | length 134
  Top Layer w20: C12.2@555,594.68 C12.2@555,598.62
  Signal Layer 2 w12: v2@637.84,720 v2(640,720) v2@641.53,718.47
  Bottom Layer w10: C1.2@198.74,895 198.74,866.5 225.24,840 v2(240,840)
  Bottom Layer w12: v2(570,370) R12.1@570,414.92
  Bottom Layer w25: C14.1@145,727.13 C14.1@145.04,727.09
  other v1: 407.63,340 620,505 285,545 325,680
  other v2: 240.7,872.5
